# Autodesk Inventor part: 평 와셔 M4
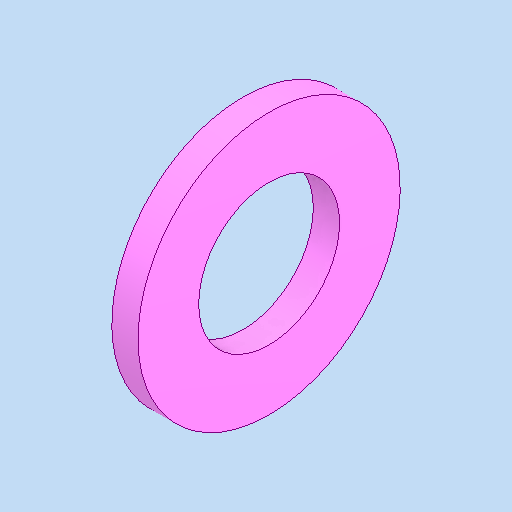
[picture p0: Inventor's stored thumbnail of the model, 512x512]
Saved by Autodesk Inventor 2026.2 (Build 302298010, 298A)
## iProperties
Created: 2026-03
Part Number: 평 와셔 M4
Material: 강철, 연강
Description: 평면 와셔
Document SubType Name: Modeling
Designer: PC-2-03
Density: 7.85 g/cm^3
Appearance: 기본값
Author: jhkim
Sending System: Autodesk Inventor 2026
Preprocessor: ST-DEVELOPER v20.1
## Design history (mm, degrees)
feature "Solid1"
node "솔리드1"
